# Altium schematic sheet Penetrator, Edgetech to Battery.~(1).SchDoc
size B; Organization: Monterey Bay Aquarium Research Institute; Address1: 7700 Sandholdt Rd; Address2: Moss Landing, CA 95039-9644; CompanyName: MBARI
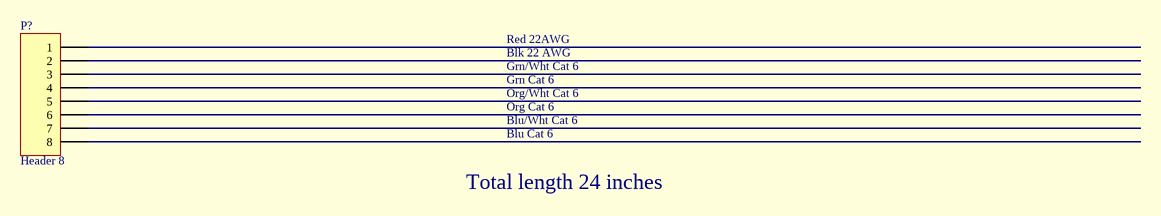
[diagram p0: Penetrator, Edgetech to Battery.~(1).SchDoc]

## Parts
P?  Header 8  [HDR1X8]

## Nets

Not connected (* = marked no-connect by the designer): P? 1 2 3 4 5 6 7 8

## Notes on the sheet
- Red 22AWG
- Blk 22 AWG
- Grn/Wht Cat 6
- Grn Cat 6
- Org/Wht Cat 6
- Org Cat 6
- Blu/Wht Cat 6
- Blu Cat 6
- Total length 24 inches

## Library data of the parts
P? = Header 8: Header, 8-Pin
